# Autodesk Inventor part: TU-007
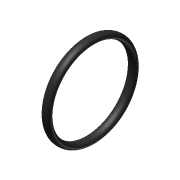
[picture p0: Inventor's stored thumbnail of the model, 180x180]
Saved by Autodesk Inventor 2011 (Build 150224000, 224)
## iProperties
Created: 2009-11
Part Number: TU-007
Material: Rubber
Document SubType Name: Modeling
Designer: t_jahrl
Density: 0.93 g/cm^3
Description: Gland O-ring
Mass: 0.921 g
Surface Area: 12.6325 cm^2
Volume: 0.990322 cm^3
Author: t_jahrl
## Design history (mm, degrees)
sketch "Sketch1"
  geometry: L1 (-13.585, 0)-(13.585, 0) reference; L2 (-9.704, 20.425)-(9.704, 20.425); L3 (-9.704, 20.35)-(-2, 20.35); L4 (2, 20.35)-(2, 17.8); L5 (2, 17.8)-(-2, 17.8); L6 (-2, 17.8)-(-2, 20.35); L7 (0, -4.085)-(0, 24.51) reference; L8 (2, 20.35)-(9.704, 20.35); L9 (-2, 19.113)-(2, 19.113); 3 further points; 1 other entity
  constraints: 14 end point, 5 parallel, 3 horizontal, 3 point on line, 2 perpendicular, 1 collinear, 1 midpoint, 4 other
  dimensions: "d0" = 40.85 diameter of L2 L1; "d2" = 40.7 diameter of L8 L1; "d3" = 4 distance between parallel lines of L6 L4; "d4" = 2.55 distance of L4.start L4.end; "d6" = 2.625 distance between parallel lines of L5 L2 (derived); "d8" = 1.3125 distance between parallel lines of L2 L9 (= 0.5 x d6)
revolve "Revolution1" sketch "Sketch1" stored, may be unused: angle "d5" = 90 deg
body "Solid1"
